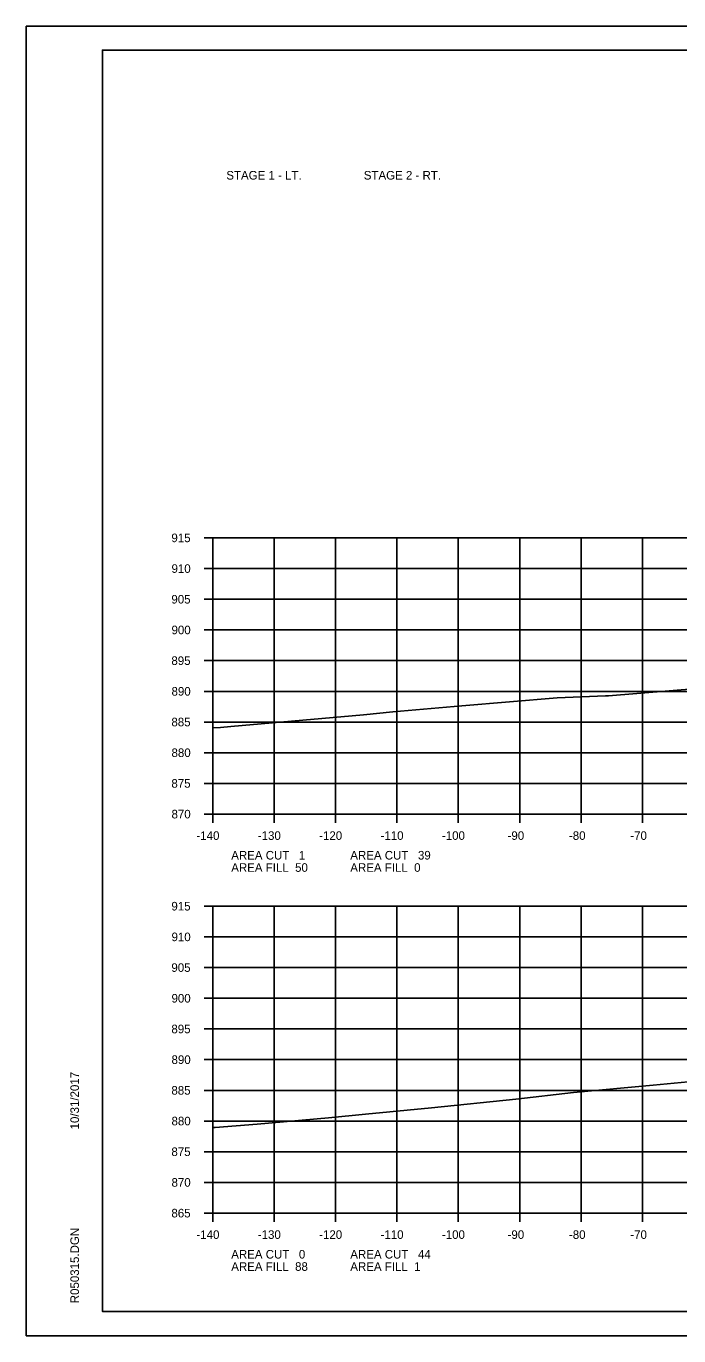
# Model space of a CAD drawing. Extents: x 1486524 to 1499135, y 326561 to 337924.
# Drawn here: x 1488812.5 to 1488918.8, y 330645.9 to 330859.3 of the extents above; entities that cross this region are included whole.
import ezdxf

# ---------------------------------------------------------------- set-up
doc = ezdxf.new("R2010")
doc.units = 0
for name, color, linetype in [('Default', 7, 'Continuous'), ('E_Const Align', 7, 'Continuous'), ('E_Const Align Station', 7, 'Continuous'), ('E_Ownership Information', 7, 'Continuous'), ('E_Property Line', 7, 'Continuous'), ('E_Quarter Calls', 7, 'Continuous'), ('E_Tract Number', 7, 'Continuous')]:
    doc.layers.add(name, color=color, linetype=linetype)

msp = doc.modelspace()

# ---------------------------------------------------------------- linework, layer by layer
at = {"layer": 'E_Const Align'}
for p, q in [((1488841.49, 330775.91), (1488842.89, 330775.91)), ((1488842.89, 330730.91), (1488842.89, 330775.91)), ((1488841.49, 330770.91), (1488842.89, 330770.91)), ((1488841.49, 330765.91), (1488842.89, 330765.91)), ((1488841.49, 330760.91), (1488842.89, 330760.91)), ((1488841.49, 330755.91), (1488842.89, 330755.91)), ((1488841.49, 330750.91), (1488842.89, 330750.91)), ((1488841.49, 330745.91), (1488842.89, 330745.91)), ((1488841.49, 330740.91), (1488842.89, 330740.91)), ((1488841.49, 330735.91), (1488842.89, 330735.91)), ((1488841.49, 330730.91), (1488842.89, 330730.91)), ((1488842.89, 330730.91), (1489122.89, 330730.91)), ((1488842.89, 330729.51), (1488842.89, 330730.91)), ((1488852.89, 330729.51), (1488852.89, 330730.91)), ((1488862.89, 330729.51), (1488862.89, 330730.91)), ((1488872.89, 330729.51), (1488872.89, 330730.91)), ((1488882.89, 330729.51), (1488882.89, 330730.91)), ((1488892.89, 330729.51), (1488892.89, 330730.91)), ((1488902.89, 330729.51), (1488902.89, 330730.91)), ((1488912.89, 330729.51), (1488912.89, 330730.91)), ((1488841.49, 330715.91), (1488842.89, 330715.91)), ((1488842.89, 330665.91), (1488842.89, 330715.91)), ((1488841.49, 330710.91), (1488842.89, 330710.91)), ((1488841.49, 330705.91), (1488842.89, 330705.91)), ((1488841.49, 330700.91), (1488842.89, 330700.91)), ((1488841.49, 330695.91), (1488842.89, 330695.91)), ((1488841.49, 330690.91), (1488842.89, 330690.91)), ((1488841.49, 330685.91), (1488842.89, 330685.91)), ((1488841.49, 330680.91), (1488842.89, 330680.91)), ((1488841.49, 330675.91), (1488842.89, 330675.91)), ((1488841.49, 330670.91), (1488842.89, 330670.91)), ((1488841.49, 330665.91), (1488842.89, 330665.91)), ((1488842.89, 330665.91), (1489122.89, 330665.91)), ((1488842.89, 330664.51), (1488842.89, 330665.91)), ((1488852.89, 330664.51), (1488852.89, 330665.91)), ((1488862.89, 330664.51), (1488862.89, 330665.91)), ((1488872.89, 330664.51), (1488872.89, 330665.91)), ((1488882.89, 330664.51), (1488882.89, 330665.91)), ((1488892.89, 330664.51), (1488892.89, 330665.91)), ((1488902.89, 330664.51), (1488902.89, 330665.91)), ((1488912.89, 330664.51), (1488912.89, 330665.91))]:
    msp.add_line(p, q, dxfattribs=at)
at = {"layer": 'E_Ownership Information'}
for p, q in [((1488842.89, 330775.91), (1489122.89, 330775.91)), ((1488842.89, 330730.91), (1488842.89, 330775.91)), ((1488852.89, 330730.91), (1488852.89, 330775.91)), ((1488862.89, 330730.91), (1488862.89, 330775.91)), ((1488872.89, 330730.91), (1488872.89, 330775.91)), ((1488882.89, 330730.91), (1488882.89, 330775.91)), ((1488892.89, 330730.91), (1488892.89, 330775.91)), ((1488902.89, 330730.91), (1488902.89, 330775.91)), ((1488912.89, 330730.91), (1488912.89, 330775.91)), ((1488842.89, 330770.91), (1489122.89, 330770.91)), ((1488842.89, 330765.91), (1489122.89, 330765.91)), ((1488842.89, 330760.91), (1489122.89, 330760.91)), ((1488842.89, 330755.91), (1489122.89, 330755.91)), ((1488842.89, 330750.91), (1489122.89, 330750.91)), ((1488842.89, 330745.91), (1489122.89, 330745.91)), ((1488842.89, 330740.91), (1489122.89, 330740.91)), ((1488842.89, 330735.91), (1489122.89, 330735.91)), ((1488842.89, 330730.91), (1489122.89, 330730.91)), ((1488842.89, 330715.91), (1489122.89, 330715.91)), ((1488842.89, 330665.91), (1488842.89, 330715.91)), ((1488852.89, 330665.91), (1488852.89, 330715.91)), ((1488862.89, 330665.91), (1488862.89, 330715.91)), ((1488872.89, 330665.91), (1488872.89, 330715.91)), ((1488882.89, 330665.91), (1488882.89, 330715.91)), ((1488892.89, 330665.91), (1488892.89, 330715.91)), ((1488902.89, 330665.91), (1488902.89, 330715.91)), ((1488912.89, 330665.91), (1488912.89, 330715.91)), ((1488842.89, 330710.91), (1489122.89, 330710.91)), ((1488842.89, 330705.91), (1489122.89, 330705.91)), ((1488842.89, 330700.91), (1489122.89, 330700.91)), ((1488842.89, 330695.91), (1489122.89, 330695.91)), ((1488842.89, 330690.91), (1489122.89, 330690.91)), ((1488842.89, 330685.91), (1489122.89, 330685.91)), ((1488842.89, 330680.91), (1489122.89, 330680.91)), ((1488842.89, 330675.91), (1489122.89, 330675.91)), ((1488842.89, 330670.91), (1489122.89, 330670.91)), ((1488842.89, 330665.91), (1489122.89, 330665.91))]:
    msp.add_line(p, q, dxfattribs=at)
at = {"layer": 'E_Property Line'}
for p, q in [((1488824.89, 330855.37), (1489141.07, 330855.37)), ((1488824.89, 330649.91), (1488824.89, 330855.37)), ((1488824.89, 330649.91), (1488824.89, 330649.91)), ((1489141.07, 330649.91), (1488824.89, 330649.91))]:
    msp.add_line(p, q, dxfattribs=at)
at = {"layer": 'E_Quarter Calls'}
for p, q in [((1488812.48, 330859.26), (1489145.82, 330859.26)), ((1488812.48, 330645.93), (1489145.82, 330645.93))]:
    msp.add_line(p, q, dxfattribs=at)
for points in [[(1488812.48, 330859.26), (1489145.82, 330859.26), (1489145.82, 330645.93), (1488812.48, 330645.93)], [(1489058.81, 330855.37), (1489058.81, 330845.49), (1489094.54, 330845.49), (1489094.54, 330842.57), (1489117.74, 330842.57), (1489117.74, 330818.24), (1489141.07, 330818.24), (1489141.07, 330649.91), (1488824.89, 330649.91), (1488824.89, 330855.37)]]:
    msp.add_lwpolyline(points, close=True, dxfattribs=at)
at = {"layer": 'E_Tract Number'}
for points in [[(1488842.89, 330744.94), (1488844.13, 330745.04), (1488845.85, 330745.18), (1488867.47, 330747.1), (1488872.21, 330747.57), (1488883.44, 330748.53), (1488898.98, 330749.85), (1488906.9, 330750.16), (1488907.19, 330750.17), (1488907.37, 330750.19), (1488921.87, 330751.35)], [(1488842.89, 330679.86), (1488843.25, 330679.88), (1488850.12, 330680.41), (1488861.73, 330681.46), (1488867.77, 330682.05), (1488878.53, 330683.08), (1488892.25, 330684.49), (1488901.64, 330685.55), (1488914.63, 330686.78), (1488922.62, 330687.49)]]:
    msp.add_lwpolyline(points, dxfattribs=at)

# ---------------------------------------------------------------- texts
at = {"layer": 'Default'}
for s, p in [('STAGE 1 - LT.', (1488845.09, 330834.28)), ('STAGE 2 - RT.', (1488867.49, 330834.28))]:
    msp.add_text(s, height=1.4, dxfattribs=at).set_placement(p)
at = {"layer": 'E_Const Align Station'}
for s, p in [('915', (1488836.14, 330775.21)), ('910', (1488836.16, 330770.21)), ('905', (1488836.14, 330765.21)), ('900', (1488836.16, 330760.21)), ('895', (1488836.14, 330755.21)), ('890', (1488836.16, 330750.21)), ('885', (1488836.14, 330745.21)), ('880', (1488836.16, 330740.21)), ('875', (1488836.14, 330735.21)), ('870', (1488836.16, 330730.21)), ('-140', (1488840.22, 330726.71)), ('-130', (1488850.22, 330726.71)), ('-120', (1488860.22, 330726.71)), ('-110', (1488870.22, 330726.71)), ('-100', (1488880.22, 330726.71)), ('-90', (1488890.92, 330726.71)), ('-80', (1488900.92, 330726.71)), ('-70', (1488910.92, 330726.71)), ('AREA CUT   1', (1488845.89, 330723.51)), ('     AREA CUT   39', (1488862.69, 330723.51)), ('AREA FILL  50', (1488845.89, 330721.51)), ('     AREA FILL  0', (1488862.69, 330721.51)), ('915', (1488836.14, 330715.21)), ('910', (1488836.16, 330710.21)), ('905', (1488836.14, 330705.21)), ('900', (1488836.16, 330700.21)), ('895', (1488836.14, 330695.21)), ('890', (1488836.16, 330690.21)), ('885', (1488836.14, 330685.21)), ('880', (1488836.16, 330680.21)), ('875', (1488836.14, 330675.21)), ('870', (1488836.16, 330670.21)), ('865', (1488836.14, 330665.21)), ('-140', (1488840.22, 330661.71)), ('-130', (1488850.22, 330661.71)), ('-120', (1488860.22, 330661.71)), ('-110', (1488870.22, 330661.71)), ('-100', (1488880.22, 330661.71)), ('-90', (1488890.92, 330661.71)), ('-80', (1488900.92, 330661.71)), ('-70', (1488910.92, 330661.71)), ('AREA CUT   0', (1488845.89, 330658.51)), ('     AREA CUT   44', (1488862.69, 330658.51)), ('AREA FILL  88', (1488845.89, 330656.51)), ('     AREA FILL  1', (1488862.69, 330656.51))]:
    msp.add_text(s, height=1.4, dxfattribs=at).set_placement(p)
at = {"layer": 'E_Property Line'}
for s, p in [('10/31/2017', (1488821.08, 330679.55)), ('R050315.DGN', (1488821.08, 330651.23))]:
    msp.add_text(s, height=1.4, rotation=90, dxfattribs=at).set_placement(p)

doc.saveas('drawing.dxf')
